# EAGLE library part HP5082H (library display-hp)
LED DISPLAY 1-character dot matrix, 2 decimal points
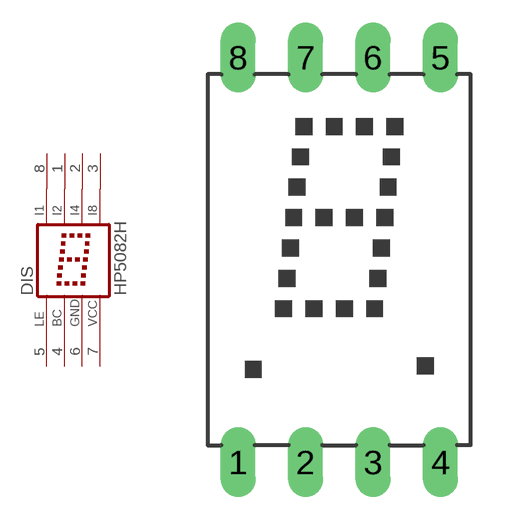
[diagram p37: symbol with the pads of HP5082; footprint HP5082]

Designator prefix DIS

## HP5082H (OC_FARNELL: unknown; OC_NEWARK: unknown)  [HP5082]
1  I2  in
2  I4  in
3  I8  in
4  BC  in
5  LE  in
6  GND  pwr
7  VCC  pwr
8  I1  in

## Footprint HP5082 (pad centres in mm)
LED DISPLAY 8-mm 1 character dot matrix, 2 decimal points
drill 0.813 long: 1 -3.81,-7.62; 2 -1.27,-7.62; 3 1.27,-7.62; 4 3.81,-7.62; 5 3.81,7.62; 6 1.27,7.62; 7 -1.27,7.62; 8 -3.81,7.62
